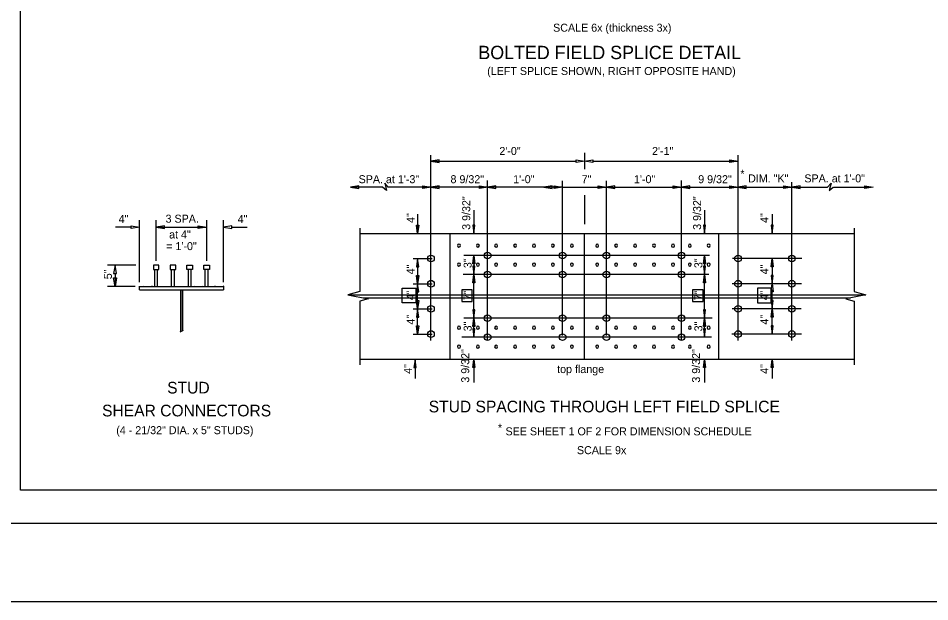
# Model space of a CAD drawing. Extents: x 4944 to 17449, y 3824 to 49087.
# Drawn here: x 6215 to 7527, y 8331 to 9172 of the extents above; entities that cross this region are included whole.
import ezdxf

# ---------------------------------------------------------------- set-up
doc = ezdxf.new("R2010")
doc.units = 0
for name, color, linetype in [('1', 7, 'Continuous'), ('2', 7, 'Continuous'), ('36_S_LINES', 7, 'Continuous'), ('37_S_TXT', 7, 'Continuous'), ('3A', 7, 'Continuous'), ('7', 7, 'Continuous'), ('BEAM', 7, 'Continuous'), ('DIM', 7, 'Continuous'), ('Level 14', 7, 'Continuous'), ('Level 25', 7, 'Continuous'), ('Level 35', 7, 'Continuous')]:
    doc.layers.add(name, color=color, linetype=linetype)

# ---------------------------------------------------------------- blocks, each defined once
blk = doc.blocks.new('4MH')
at = {"layer": 'Level 35'}
for radius, start, end in [(0.0945, 112.5426, 157.4574), (0.06, 112.5426, 157.4574), (0.06, 22.5426, 67.4574), (0.0945, 22.5426, 67.4574), (0.0945, 202.5426, 247.4574), (0.06, 202.5426, 247.4574), (0.06, 292.5426, 337.4574), (0.0945, 292.5426, 337.4574)]:
    blk.add_arc((0, 0), radius, start, end, dxfattribs=at)

msp = doc.modelspace()

# ---------------------------------------------------------------- linework, layer by layer
at = {"layer": '1'}
for centre, start, end in [((6849.4, 8844.6), 0, 180), ((6849.4, 8844.6), 180, 0), ((6876.6, 8844.5), 0, 180), ((6876.6, 8844.5), 180, 0), ((6902.8, 8844.4), 0, 180), ((6930.1, 8844.5), 0, 180), ((6930.1, 8844.5), 180, 0), ((6957.4, 8844.4), 0, 180), ((6984.6, 8844.5), 0, 180), ((6984.6, 8844.5), 180, 0), ((7011.9, 8844.4), 0, 180), ((7048.3, 8844.4), 0, 180), ((7075.6, 8844.5), 0, 180), ((7075.6, 8844.5), 180, 0), ((7102.9, 8844.4), 0, 180), ((7130.2, 8844.5), 0, 180), ((7130.2, 8844.5), 180, 0), ((7157.5, 8844.4), 0, 180), ((7181.7, 8844.4), 0, 180), ((7208.9, 8844.5), 0, 180), ((7208.9, 8844.5), 180, 0), ((6902.8, 8844.4), 180, 0), ((6957.4, 8844.4), 180, 0), ((7011.9, 8844.4), 180, 0), ((7048.3, 8844.4), 180, 0), ((7102.9, 8844.4), 180, 0), ((7157.5, 8844.4), 180, 0), ((7181.7, 8844.4), 180, 0), ((6849.4, 8817.2), 0, 180), ((6876.6, 8817.1), 0, 180), ((6902.8, 8817.1), 0, 180), ((6930.1, 8817.1), 0, 180), ((6957.4, 8817.1), 0, 180), ((6984.6, 8817.1), 0, 180), ((7011.9, 8817.1), 0, 180), ((7048.3, 8817.1), 0, 180), ((7075.6, 8817.1), 0, 180), ((7102.9, 8817.1), 0, 180), ((7130.2, 8817.1), 0, 180), ((7157.5, 8817.1), 0, 180), ((7181.7, 8817.1), 0, 180), ((7208.9, 8817.1), 0, 180), ((6849.4, 8817.2), 180, 0), ((6876.6, 8817.1), 180, 0), ((6902.8, 8817.1), 180, 0), ((6930.1, 8817.1), 180, 0), ((6957.4, 8817.1), 180, 0), ((6984.6, 8817.1), 180, 0), ((7011.9, 8817.1), 180, 0), ((7048.3, 8817.1), 180, 0), ((7075.6, 8817.1), 180, 0), ((7102.9, 8817.1), 180, 0), ((7130.2, 8817.1), 180, 0), ((7157.5, 8817.1), 180, 0), ((7181.7, 8817.1), 180, 0), ((7208.9, 8817.1), 180, 0), ((6849.4, 8726.3), 0, 180), ((6876.6, 8726.3), 0, 180), ((6902.8, 8726.2), 0, 180), ((6930.1, 8726.3), 0, 180), ((6957.4, 8726.3), 0, 180), ((6984.6, 8726.3), 0, 180), ((7011.9, 8726.3), 0, 180), ((7048.3, 8726.3), 0, 180), ((7075.6, 8726.3), 0, 180), ((7102.9, 8726.3), 0, 180), ((7130.2, 8726.3), 0, 180), ((7157.5, 8726.2), 0, 180), ((7181.7, 8726.2), 0, 180), ((7208.9, 8726.3), 0, 180), ((6849.4, 8726.3), 180, 0), ((6876.6, 8726.3), 180, 0), ((6902.8, 8726.2), 180, 0), ((6930.1, 8726.3), 180, 0), ((6957.4, 8726.3), 180, 0), ((6984.6, 8726.3), 180, 0), ((7011.9, 8726.3), 180, 0), ((7048.3, 8726.3), 180, 0), ((7075.6, 8726.3), 180, 0), ((7102.9, 8726.3), 180, 0), ((7130.2, 8726.3), 180, 0), ((7157.5, 8726.2), 180, 0), ((7181.7, 8726.2), 180, 0), ((7208.9, 8726.3), 180, 0), ((6849.4, 8699), 0, 180), ((6876.6, 8698.9), 0, 180), ((6902.8, 8698.8), 0, 180), ((6930.1, 8698.9), 0, 180), ((6957.4, 8699), 0, 180), ((6984.6, 8698.9), 0, 180), ((7011.9, 8699), 0, 180), ((7048.3, 8699), 0, 180), ((7075.6, 8698.9), 0, 180), ((7102.9, 8699), 0, 180), ((7130.2, 8698.9), 0, 180), ((7157.5, 8698.8), 0, 180), ((7181.7, 8698.8), 0, 180), ((7208.9, 8698.9), 0, 180), ((6849.4, 8699), 180, 0), ((6876.6, 8698.9), 180, 0), ((6902.8, 8698.8), 180, 0), ((6930.1, 8698.9), 180, 0), ((6957.4, 8699), 180, 0), ((6984.6, 8698.9), 180, 0), ((7011.9, 8699), 180, 0), ((7048.3, 8699), 180, 0), ((7075.6, 8698.9), 180, 0), ((7102.9, 8699), 180, 0), ((7130.2, 8698.9), 180, 0), ((7157.5, 8698.8), 180, 0), ((7181.7, 8698.8), 180, 0), ((7208.9, 8698.9), 180, 0)]:
    msp.add_arc(centre, 2.13, start, end, dxfattribs=at)
at = {"layer": '2'}
msp.add_line((7030.1, 8680.8), (7030.1, 8862.1), dxfattribs=at)
at = {"layer": '36_S_LINES'}
for p, q in [((7030.1, 8978.3), (7030.1, 8954.5)), ((6809.1, 8966), (7018.1, 8966)), ((7042.1, 8966), (7251.1, 8966)), ((6739.3, 8928.6), (6693.2, 8928.6)), ((6745, 8924), (6739.3, 8928.6)), ((6742.5, 8934.6), (6745, 8924)), ((6747.3, 8928.6), (6742.5, 8934.6)), ((6998.7, 8928.6), (6747.4, 8928.6)), ((6998.7, 8928.6), (7061.6, 8928.6)), ((7061.6, 8928.6), (7380.1, 8928.6)), ((7380.1, 8928.6), (7385, 8934.6)), ((7385, 8934.6), (7382.4, 8924)), ((7382.4, 8924), (7388.2, 8928.6)), ((7388.4, 8928.6), (7441.2, 8928.6)), ((7030.1, 8917.4), (7030.1, 8875.2)), ((6789.9, 8889.7), (6789.9, 8862.1)), ((6870.7, 8895.7), (6870.7, 8862.1)), ((7202.9, 8895.7), (7202.9, 8862.1)), ((7300.1, 8889.7), (7300.1, 8862.1)), ((6377.3, 8871.1), (6354.8, 8871.1)), ((6389.4, 8791.9), (6389.4, 8881)), ((6413.4, 8822.4), (6413.4, 8881)), ((6413.4, 8871.1), (6486.2, 8871.1)), ((6486.2, 8822.4), (6486.2, 8881)), ((6510.2, 8791.9), (6510.2, 8881)), ((6522.3, 8871.1), (6544.3, 8871.1)), ((6706.5, 8869.7), (6706.5, 8778.3)), ((7418.2, 8869.7), (7418.2, 8778.3)), ((6789.9, 8826), (6789.9, 8789.6)), ((6870.7, 8830.2), (6870.7, 8802.9)), ((7202.9, 8830.2), (7202.9, 8802.9)), ((7300.1, 8826), (7300.1, 8789.6)), ((6384, 8816.3), (6343.5, 8816.3)), ((6354.2, 8804.2), (6354.2, 8785.8)), ((6870.7, 8748), (6870.7, 8802.9)), ((7202.9, 8748), (7202.9, 8802.9)), ((6383.3, 8785.8), (6343.5, 8785.8)), ((6789.9, 8753.3), (6789.9, 8780.6)), ((7300.1, 8753.3), (7300.1, 8780.6)), ((6706.5, 8778.3), (6689.4, 8773.5)), ((6689.4, 8773.5), (6718.5, 8767.8)), ((6718.5, 8767.8), (6706.5, 8764.4)), ((7435.2, 8773.5), (7406.1, 8767.8)), ((7406.1, 8767.8), (7418.2, 8764.4)), ((7418.2, 8778.3), (7435.2, 8773.5)), ((6706.5, 8764.4), (6706.5, 8672.7)), ((6789.9, 8716.8), (6789.9, 8753.3)), ((7300.1, 8716.8), (7300.1, 8753.3)), ((7418.2, 8764.4), (7418.2, 8672.7)), ((6870.7, 8712.7), (6870.7, 8740)), ((7202.9, 8712.7), (7202.9, 8740)), ((6452.3, 8722.4), (6447.3, 8720)), ((6786.1, 8680.7), (6786.1, 8653.1)), ((6870.7, 8680.7), (6870.7, 8647.2)), ((7202.9, 8680.7), (7202.9, 8647.2)), ((7300.1, 8680.7), (7300.1, 8653.1))]:
    msp.add_line(p, q, dxfattribs=at)
for points in [[(6821, 8964), (6821, 8968), (6809, 8966)], [(7018.1, 8968), (7030.1, 8966), (7018.1, 8964)], [(7042.1, 8964), (7030.1, 8966), (7042.1, 8968)], [(7239.1, 8968), (7251.1, 8966), (7239.1, 8964)], [(6705.2, 8926.6), (6705.2, 8930.6), (6693.2, 8928.6)], [(6797.3, 8926.6), (6797.3, 8930.6), (6809.3, 8928.6)], [(6821, 8926.6), (6821, 8930.6), (6809, 8928.6)], [(6878.8, 8926.6), (6878.8, 8930.6), (6890.8, 8928.6)], [(6902.5, 8926.6), (6902.5, 8930.6), (6890.5, 8928.6)], [(6983.6, 8926.6), (6983.6, 8930.6), (6971.6, 8928.6)], [(6986.6, 8926.6), (6986.6, 8930.6), (6998.6, 8928.6)], [(7049.6, 8926.6), (7049.6, 8930.6), (7061.6, 8928.6)], [(7073.6, 8926.6), (7073.6, 8930.6), (7061.6, 8928.6)], [(7157.8, 8926.6), (7157.8, 8930.6), (7169.8, 8928.6)], [(7181.5, 8926.6), (7181.5, 8930.6), (7169.5, 8928.6)], [(7239.3, 8926.6), (7239.3, 8930.6), (7251.3, 8928.6)], [(7263, 8926.6), (7263, 8930.6), (7251, 8928.6)], [(7316.9, 8926.6), (7316.9, 8930.6), (7328.9, 8928.6)], [(7340.6, 8926.6), (7340.6, 8930.6), (7328.6, 8928.6)], [(7433.7, 8926.6), (7433.7, 8930.6), (7445.7, 8928.6)], [(6377.3, 8869.1), (6377.3, 8873.1), (6389.4, 8871.1)], [(6425.5, 8869.1), (6425.5, 8873.1), (6413.4, 8871.1)], [(6474, 8869.1), (6474, 8873.1), (6486.2, 8871.1)], [(6522.3, 8869.1), (6522.3, 8873.1), (6510.2, 8871.1)], [(6788.4, 8874.1), (6791.4, 8874.1), (6789.9, 8862.1)], [(6872.2, 8874.1), (6869.1, 8874.1), (6870.7, 8862.1)], [(7204.4, 8874.1), (7201.4, 8874.1), (7202.9, 8862.1)], [(7301.6, 8874.1), (7298.6, 8874.1), (7300.1, 8862.1)], [(6788.4, 8813.8), (6791.4, 8813.8), (6789.9, 8825.8)], [(6872.2, 8818.2), (6869.1, 8818.2), (6870.7, 8830.2)], [(7204.4, 8818.2), (7201.4, 8818.2), (7202.9, 8830.2)], [(7301.6, 8813.7), (7298.6, 8813.7), (7300.1, 8825.7)], [(6352.2, 8804.2), (6356.2, 8804.2), (6354.2, 8816.3)], [(6872.2, 8814.9), (6869.1, 8814.9), (6870.7, 8802.9)], [(7204.4, 8814.9), (7201.4, 8814.9), (7202.9, 8802.9)], [(6352.2, 8797.9), (6356.2, 8797.9), (6354.2, 8785.8)], [(6788.4, 8801.6), (6791.4, 8801.6), (6789.9, 8789.6)], [(6872.2, 8790.9), (6869.1, 8790.9), (6870.7, 8802.9)], [(7204.4, 8790.9), (7201.4, 8790.9), (7202.9, 8802.9)], [(7301.6, 8801.6), (7298.6, 8801.6), (7300.1, 8789.6)], [(6788.4, 8777.7), (6791.4, 8777.7), (6789.9, 8789.7)], [(7301.6, 8777.7), (7298.6, 8777.7), (7300.1, 8789.7)], [(6788.4, 8765.3), (6791.4, 8765.3), (6789.9, 8753.3)], [(6788.4, 8741.3), (6791.4, 8741.3), (6789.9, 8753.3)], [(7301.6, 8765.3), (7298.6, 8765.3), (7300.1, 8753.3)], [(7301.6, 8741.3), (7298.6, 8741.3), (7300.1, 8753.3)], [(6872.2, 8752), (6869.1, 8752), (6870.7, 8740)], [(6872.2, 8728), (6869.1, 8728), (6870.7, 8740)], [(7204.4, 8752), (7201.4, 8752), (7202.9, 8740)], [(7204.4, 8728), (7201.4, 8728), (7202.9, 8740)], [(6788.4, 8729), (6791.4, 8729), (6789.9, 8717.1)], [(7301.6, 8729), (7298.6, 8729), (7300.1, 8717.1)], [(6872.2, 8724.7), (6869.1, 8724.7), (6870.7, 8712.7)], [(7204.4, 8724.7), (7201.4, 8724.7), (7202.9, 8712.7)], [(6784.6, 8668.7), (6787.6, 8668.7), (6786.1, 8680.7)], [(6872.2, 8668.7), (6869.1, 8668.7), (6870.7, 8680.7)], [(7204.4, 8668.7), (7201.4, 8668.7), (7202.9, 8680.7)], [(7301.6, 8668.7), (7298.6, 8668.7), (7300.1, 8680.7)]]:
    msp.add_lwpolyline(points, close=True, dxfattribs=at)
at = {"layer": '37_S_TXT'}
msp.add_lwpolyline([(5873.7, 10635.5), (9329.7, 10635.5), (9329.7, 8331.5), (5873.7, 8331.5)], close=True, dxfattribs=at)
at = {"layer": '3A'}
for p, q in [((6809.1, 8707.7), (6809.1, 8974.8)), ((7251.1, 8707.7), (7251.1, 8974.8)), ((6890.6, 8707.7), (6890.6, 8938.3)), ((6998.6, 8715.2), (6998.6, 8937.7)), ((7061.6, 8715.2), (7061.6, 8937.7)), ((7169.6, 8707.7), (7169.6, 8938.3)), ((7328.7, 8707.7), (7328.7, 8935.8)), ((6783.4, 8825.8), (6811, 8825.8)), ((7210.1, 8830.2), (6856.2, 8830.2)), ((7343.1, 8825.8), (7243.1, 8825.8)), ((7209.3, 8802.9), (6855.6, 8802.9)), ((6783.4, 8789.6), (6811, 8789.6)), ((7342.7, 8789.6), (7242.7, 8789.6)), ((6783.4, 8753.3), (6811, 8753.3)), ((7342.2, 8753.3), (7242.7, 8753.3)), ((7213.7, 8740), (6856.2, 8740)), ((6783.4, 8717.1), (6811, 8717.1)), ((7342.4, 8717.1), (7242.4, 8717.1)), ((7213.1, 8712.6), (6853.4, 8712.6))]:
    msp.add_line(p, q, dxfattribs=at)
for points in [[(6767.7, 8761.9), (6767.7, 8783), (6787.3, 8783), (6787.3, 8761.9)], [(6868.5, 8764.2), (6868.5, 8780.7), (6853.5, 8780.7), (6853.5, 8764.2)], [(7200.8, 8764.2), (7200.8, 8780.7), (7185.8, 8780.7), (7185.8, 8764.2)], [(7298.7, 8761.9), (7298.7, 8783), (7279.2, 8783), (7279.2, 8761.9)]]:
    msp.add_lwpolyline(points, close=True, dxfattribs=at)
at = {"layer": '7'}
for p, q in [((6690.2, 8773.7), (7434.4, 8773.7)), ((6711.6, 8769.2), (7413.1, 8769.2))]:
    msp.add_line(p, q, dxfattribs=at)
at = {"layer": 'DIM'}
msp.add_lwpolyline([(6030.9, 10556.3), (9294.9, 10556.3), (9294.9, 8444.3), (6030.9, 8444.3)], close=True, dxfattribs=at)
at = {"layer": 'Level 14'}
msp.add_lwpolyline([(9242.1, 8492.3), (6218.1, 8492.3), (6218.1, 10508.3), (9242.1, 10508.3)], close=True, dxfattribs=at)
at = {"layer": 'Level 25'}
for p, q in [((6706.5, 8862.1), (7418.2, 8862.1)), ((6836.7, 8680.8), (6836.7, 8862.1)), ((7223.6, 8680.8), (7223.6, 8862.1)), ((6417.4, 8816.3), (6409.4, 8816.3)), ((6409.4, 8816.3), (6409.4, 8810.3)), ((6409.4, 8810.3), (6417.4, 8810.3)), ((6411.4, 8785.8), (6411.4, 8810.3)), ((6415.4, 8785.8), (6415.4, 8810.3)), ((6417.4, 8810.3), (6417.4, 8816.3)), ((6433.8, 8816.3), (6433.8, 8810.3)), ((6441.7, 8816.3), (6433.8, 8816.3)), ((6433.8, 8810.3), (6441.7, 8810.3)), ((6435.7, 8785.8), (6435.7, 8810.3)), ((6439.8, 8785.8), (6439.8, 8810.3)), ((6441.7, 8810.3), (6441.7, 8816.3)), ((6457.8, 8816.3), (6465.8, 8816.3)), ((6457.8, 8810.3), (6457.8, 8816.3)), ((6465.8, 8810.3), (6457.8, 8810.3)), ((6459.8, 8785.8), (6459.8, 8810.3)), ((6463.8, 8785.8), (6463.8, 8810.3)), ((6465.8, 8816.3), (6465.8, 8810.3)), ((6482.2, 8810.3), (6482.2, 8816.3)), ((6482.2, 8816.3), (6490.1, 8816.3)), ((6490.1, 8810.3), (6482.2, 8810.3)), ((6484.2, 8785.8), (6484.2, 8810.3)), ((6488.2, 8785.8), (6488.2, 8810.3)), ((6490.1, 8816.3), (6490.1, 8810.3)), ((6389.4, 8785.8), (6510.2, 8785.8)), ((6389.4, 8780.9), (6389.4, 8785.8)), ((6389.4, 8780.9), (6510.2, 8780.9)), ((6448.3, 8780.9), (6448.3, 8720.4)), ((6451.3, 8780.9), (6451.3, 8721.8)), ((6451.3, 8722.3), (6451.3, 8780.9)), ((6510.2, 8785.8), (6510.2, 8780.9)), ((6706.5, 8680.8), (7418.2, 8680.8))]:
    msp.add_line(p, q, dxfattribs=at)
for centre in [(6890.6, 8830.2), (6998.6, 8830.2), (7061.6, 8830.2), (7169.6, 8830.2), (6809.1, 8825.8), (7251.1, 8825.8), (7328.7, 8825.8), (6890.6, 8802.9), (6998.6, 8802.9), (7061.6, 8802.9), (7169.6, 8802.9), (6809.1, 8789.6), (7251.1, 8789.6), (7328.7, 8789.6), (6809.1, 8753.3), (7251.1, 8753.3), (7328.7, 8753.3), (6890.6, 8740.1), (6998.6, 8740.1), (7061.6, 8740.1), (7169.6, 8740.1), (6809.1, 8717.1), (6890.6, 8712.7), (6998.6, 8712.7), (7061.6, 8712.7), (7169.6, 8712.7), (7251.1, 8717.1), (7328.7, 8717.1)]:
    msp.add_circle(centre, 4.79, dxfattribs=at)

# ---------------------------------------------------------------- block references
at = {"layer": 'DEFPOINTS', "xscale": 0.9, "yscale": 0.9}
for p in [(6389.4, 8785.8), (6395.4, 8785.8), (6401.5, 8785.8), (6407.5, 8785.8), (6413.5, 8785.8), (6419.6, 8785.8), (6425.6, 8785.8), (6431.7, 8785.8), (6437.7, 8785.8), (6443.7, 8785.8), (6449.8, 8785.8), (6455.8, 8785.8), (6461.9, 8785.8), (6467.9, 8785.8), (6473.9, 8785.8), (6480, 8785.8), (6486, 8785.8), (6492, 8785.8), (6498.1, 8785.8), (6504.1, 8785.8), (6510.2, 8785.8)]:
    msp.add_blockref('4MH', p, dxfattribs=at)
at = {"layer": 'Level 35', "xscale": 5, "yscale": 5}
msp.add_blockref('4MH', (6786.1, 8680.8), dxfattribs=at)

# ---------------------------------------------------------------- texts
at = {"layer": '36_S_LINES'}
for p in [(7254.4, 8942.2), (6905.4, 8576.4)]:
    msp.add_text('*', height=11.5, dxfattribs=at).set_placement(p)
at = {"layer": '3A'}
for s, p in [('(LEFT SPLICE SHOWN, RIGHT OPPOSITE HAND)', (6890, 9090.2)), ('2\'-0"', (6907.5, 8975)), ('2\'-1"', (7127.3, 8975)), ('SPA. at 1\'-3"', (6704.9, 8934.4)), ('8 9/32"', (6837.2, 8934.4)), ('1\'-0"', (6927.4, 8934.4)), ('7"', (7026, 8934.4)), ('1\'-0"', (7101.3, 8934.4)), ('9 9/32"', (7193.8, 8934.4)), ('DIM. "K"', (7265.6, 8935.5)), ('SPA. at 1\'-0"', (7346.6, 8935.6)), ('4"', (6359.4, 8877.1)), ('3 SPA.', (6427, 8877.5)), ('4"', (6530.8, 8877.1)), ('at 4"', (6432.1, 8854.8)), ('= 1\'-0"', (6427.9, 8838)), ('(4 - 21/32" DIA. x 5" STUDS)', (6356, 8572.9)), ('SEE SHEET 1 OF 2 FOR DIMENSION SCHEDULE', (6916.4, 8571.2))]:
    msp.add_text(s, height=11.52, dxfattribs=at).set_placement(p)
for s, p in [('3 9/32"', (6865.6, 8867.2)), ('3 9/32"', (7197.9, 8867.2)), ('4"', (6785.4, 8877.2)), ('4"', (7294.7, 8877.2)), ('3"', (6867.6, 8812.1)), ('3"', (7199.8, 8812.1)), ('5"', (6349.7, 8796.1)), ('4"', (6785.4, 8803.1)), ('4"', (7294.7, 8803.1)), ('4"', (6785.4, 8765.9)), ('7"', (6867.6, 8766)), ('7"', (7199.8, 8766)), ('4"', (7294.7, 8765.9)), ('4"', (6785.4, 8730.8)), ('4"', (7294.7, 8730.8)), ('3"', (6867.6, 8721)), ('3"', (7199.8, 8721)), ('3 9/32"', (6864.1, 8647.1)), ('3 9/32"', (7196.4, 8647.1)), ('4"', (6781.6, 8659.8)), ('4"', (7294.7, 8659.8))]:
    msp.add_text(s, height=11.52, rotation=90, dxfattribs=at).set_placement(p)
at = {"layer": 'BEAM'}
for s, height, p in [('BOLTED FIELD SPLICE DETAIL', 19.2, (6877.3, 9113.1)), ('STUD', 16.8, (6429.3, 8631.5)), ('SHEAR CONNECTORS', 16.8, (6335.6, 8598.5)), ('STUD SPACING THROUGH LEFT FIELD SPLICE', 16.8, (6805.8, 8604.3))]:
    msp.add_text(s, height=height, dxfattribs=at).set_placement(p)
at = {"layer": 'DEFPOINTS'}
for s, p in [('SCALE 6x (thickness 3x)', (6984.9, 9152.6)), ('top flange', (6990.7, 8660.9)), ('SCALE 9x', (7019.2, 8544.1))]:
    msp.add_text(s, height=11.52, dxfattribs=at).set_placement(p)

doc.saveas('drawing.dxf')
